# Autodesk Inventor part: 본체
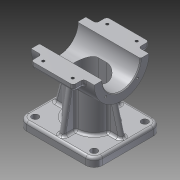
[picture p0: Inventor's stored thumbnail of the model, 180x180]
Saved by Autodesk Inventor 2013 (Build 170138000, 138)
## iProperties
Company: 한국ATC센터
Created: 2014-02
Part Number: 본체
Document SubType Name: Modeling
Designer: KYOUNG IL JANG
Density: 2.71 g/cm^3
Material: 알루미늄-6061
Vendor: CBT Solutions
Mass: 478.987 g
Surface Area: 471.046 cm^2
Volume: 176.748 cm^3
Author: KYOUNG IL JANG
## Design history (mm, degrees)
sketch "스케치1"
  geometry: L1 (-45, 40)-(45, 40); L2 (45, 40)-(45, -40); L3 (45, -40)-(-45, -40); L4 (-45, -40)-(-45, 40); 3 further points
  constraints: 8 end point, 2 midpoint, 2 parallel, 1 horizontal, 1 horizontal alignment, 1 perpendicular, 1 vertical alignment
  dimensions: "d0" = 90 distance of L2.end L3.end; "d1" = 80 distance of L1.end L2.end
extrude "돌출1" new body sketch "스케치1" distance "d2" = 10; taper "d3" = 0 deg
sketch "스케치2"
  geometry: L1 (40, 0)-(-40, 0) reference; C1 r 32.5 at (0, 80); 2 further points
  constraints: 1 centre point, 1 midpoint, 1 vertical alignment
  dimensions: "d4" = 65 diameter of C1; "d5" = 80 distance from line of C1.centre L1
extrude "돌출2" join sketch "스케치2" stored distance "d6" = 75; taper "d7" = 0 deg
sketch "스케치3"
  geometry: L1 (-5, -20)-(5, -20); L2 (5, 20)-(-5, 20); A1 r 20 centre (5, 0) between (5, -20) and (5, 20); A2 r 20 centre (-5, 0) between (-5, 20) and (-5, -20); 2 further points
  constraints: 4 end point, 4 point on circle, 4 tangent, 2 centre point, 1 horizontal, 1 horizontal alignment, 1 midpoint, 1 parallel, 1 vertical alignment
  dimensions: "d8" = 20 radius of A2; "d9" = 50 dimension on A1 A2
extrude "돌출3" join sketch "스케치3" stored distance "d10" = 75; taper "d11" = 0 deg
fillet "모깎기1" dims "d12" = 10
sketch "스케치4"
  geometry: L1 (37.5, 47.5)-(-37.5, 47.5) reference; L2 (-40, 10)-(-29.952, 47.5); L3 (-45, 10)-(-35, 10) reference; 1 further point
  constraints: 2 end point, 1 midpoint, 1 point on line
  dimensions: "d105" = 5 distance of L2.start L3.start; "d106" = 75 deg angle of L3 L2
sketch "스케치5"
  geometry: L1 (-35, 10)-(-26.077, 60.603); L2 (-40, 10)-(-30, 10) reference; 2 further points
  constraints: 2 end point, 1 midpoint, 2 other
  dimensions: "d107" = 5 distance of L1.start L2.start; "d108" = 80 deg angle of L2 L1
feature "리브1" dims "d15" = 1, "d16" = 6, "d17" = 0
feature "리브2" dims "d18" = 1, "d19" = 6, "d20" = 0
fillet "모깎기2" dims "d21" = 3
fillet "모깎기3" dims "d22" = 3
fillet "모깎기4" dims "d23" = 3
fillet "모깎기5" dims "d24" = 3
fillet "모깎기6" dims "d25" = 3
fillet "모깎기7" dims "d26" = 3
sketch "스케치6"
  geometry: A1 r 10 centre (35, -30) between (35, -40) and (45, -30) reference; 1 further point
hole "구멍1" sketch "스케치6" at (35, -30) diameter "d28" = 8; stored, may be unused: countersink angle "d32" = 90 deg, drill point angle "d34" = 118 deg; dims "d29" = 6, "d30" = 4, "d31" = 2, "d33" = 8
hole "구멍2" diameter "d37" = 45; stored, may be unused: countersink angle "d41" = 90 deg, drill point angle "d43" = 118 deg; dims "d35" = 10, "d36" = 10, "d38" = 6, "d39" = 4, "d40" = 2, "d42" = 8
sketch "스케치7"
  geometry: C1 r 22.5 at (0, 0) reference; 2 further points
  dimensions: "d44" = 135 deg dimension on C1.centre point (-18.738, 18.738) point (80, 0); "d45" = 26.5 distance of point (-18.738, 18.738) C1.centre
hole "구멍3" sketch "스케치7" at (-18.738, 18.738) diameter "d46" = 2.459; stored, may be unused: countersink angle "d50" = 90 deg, drill point angle "d52" = 118 deg; dims "d47" = 8, "d48" = 4, "d49" = 2, "d51" = 10
node "작업 평면1"
sketch "스케치8"
  geometry: C1 r 10 at (0, 0); 1 further point
  constraints: 1 centre point, 1 coincident
  dimensions: "d57" = 20 diameter of C1
extrude "돌출4" join sketch "스케치8" stored distance "d58" = 75; taper "d59" = 0 deg
hole "구멍4" diameter "d62" = 8.376; stored, may be unused: countersink angle "d66" = 90 deg, drill point angle "d68" = 118 deg; dims "d60" = 10, "d61" = 10, "d63" = 7, "d64" = 4, "d65" = 2, "d67" = 10
chamfer "모따기1" distance "d69" = 1; stored, may be unused: second distance "d70" = 2, angle "d71" = 45 deg
fillet "모깎기9" dims "d72" = 3
sketch "스케치9"
  geometry: L1 (-31.623, 87.5)-(-45, 87.5); L2 (-45, 87.5)-(-45, 72.5); L3 (-45, 72.5)-(-31.623, 72.5); A1 r 32.5 centre (0, 80) between (-31.623, 87.5) and (-31.623, 72.5) reference; 1 further point
  constraints: 6 end point, 2 parallel, 2 point on circle, 1 horizontal, 1 perpendicular
  dimensions: "d73" = 15 distance of L1.end L2.end; "d74" = 45 distance from line of A1.centre L2
extrude "돌출5" join sketch "스케치9" stored distance "d75" = 50; taper "d76" = 0 deg
fillet "모깎기10" dims "d77" = 3
fillet "모깎기11" dims "d78" = 3
sketch "스케치10"
  geometry: L1 (-61.625, 62.366)-(0, 62.366); L2 (0, 62.366)-(0, -62.366); L3 (0, -62.366)-(-61.625, -62.366); L4 (-61.625, -62.366)-(-61.625, 62.366); C1 r 32.5 at (0, 0) reference; 2 further points
  constraints: 8 end point, 2 parallel, 1 coincident, 1 horizontal, 1 midpoint, 1 perpendicular
extrude "돌출6" cut sketch "스케치10" stored distance "d79" = 10; taper "d80" = 0 deg
node "작업 평면2"
sketch "스케치11"
  geometry: L1 (-5, -15)-(5, -15); L2 (5, 15)-(-5, 15); A1 r 15 centre (5, 0) between (5, -15) and (5, 15); A2 r 15 centre (-5, 0) between (-5, 15) and (-5, -15); 9 further points
  constraints: 4 end point, 4 point on circle, 3 tangent, 2 centre point, 1 coincident, 1 horizontal, 1 parallel, 2 other
  dimensions: "d82" = 15 radius of A2; "d109" = 5 dimension on A2; "d110" = 5 dimension on A1
extrude "돌출7" cut sketch "스케치11" stored distance "d83" = 10; taper "d84" = 0 deg
sketch "스케치12"
  geometry: 1 further point
hole "구멍5" sketch "스케치12" at (0, 0) diameter "d85" = 12; stored, may be unused: countersink angle "d89" = 90 deg, drill point angle "d91" = 118 deg; dims "d86" = 6, "d87" = 38, "d88" = 10, "d90" = 8
sketch "스케치13"
  geometry: L1 (-15.5, -12.5)-(-59.5, -12.5) reference; 3 further points
  constraints: 1 horizontal alignment
  dimensions: "d92" = 35 distance of point (-20, -5.5) point (-55, -5.5); "d93" = 17.5 horizontal distance of point (-37.5, 32.5) point (-55, -5.5) (= 0.5 x d92); "d94" = 7 distance from line of L1 point (-55, -5.5)
hole "구멍6" sketch "스케치13" at (-55, -5.5), (-20, -5.5) diameter "d95" = 3.242; stored, may be unused: countersink angle "d99" = 90 deg, drill point angle "d101" = 118 deg; dims "d96" = 6, "d97" = 38, "d98" = 10, "d100" = 8
sketch "스케치14"
  geometry: C1 r 10 at (0, 0); 1 further point
  constraints: 1 centre point, 1 coincident
  dimensions: "d102" = 20 diameter of C1
extrude "돌출8" cut sketch "스케치14" distance "d103" = 5; taper "d104" = 0 deg
fillet "모깎기12" dims "d111" = 3
node "솔리드1"
mirror "대칭1"
mirror "대칭2"
mirror "대칭3"
mirror "대칭4"
pattern_circular "원형 패턴1" dims angle "d54" = 360 deg
mirror "대칭5"
mirror "대칭6"
mirror "대칭7"
other parameters: "d56" = -117
